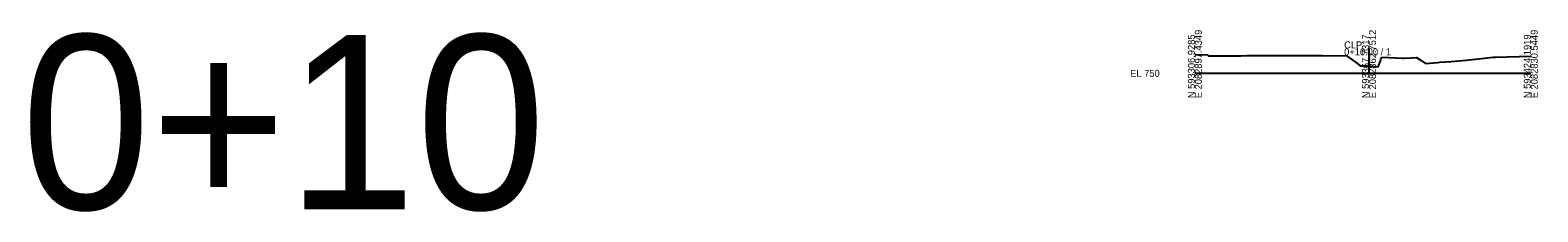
# Model space of a CAD drawing. Extents: x -577 to 1138, y -35 to 4556.
# Drawn here: x -468 to 138, y 944 to 1017 of the extents above; entities that cross this region are included whole.
import ezdxf

# ---------------------------------------------------------------- set-up
doc = ezdxf.new("R2010")
doc.units = 0
for name, color, linetype in [('GK_Cells', 7, 'Continuous'), ('SC_Scratch1', 7, 'Continuous'), ('XS_X_Ground_Line', 7, 'Continuous')]:
    doc.layers.add(name, color=color, linetype=linetype)

msp = doc.modelspace()

# ---------------------------------------------------------------- linework, layer by layer
at = {"layer": 'GK_Cells'}
for p, q in [((70, 1000), (70, 1010)), ((0, 1000), (70, 1000)), ((70, 1000), (135, 1000))]:
    msp.add_line(p, q, dxfattribs=at)
at = {"layer": 'XS_X_Ground_Line'}
for p, q in [((0, 1007.55), (0.53, 1007.54)), ((0.53, 1007.54), (5.17, 1007.37)), ((5.17, 1007.37), (5.41, 1007.02)), ((5.41, 1007.02), (6.27, 1007.01)), ((6.27, 1007.01), (6.34, 1007.01)), ((6.34, 1007.01), (6.45, 1007.01)), ((6.45, 1007.01), (6.86, 1007)), ((6.86, 1007), (8.05, 1007)), ((8.05, 1007), (17.53, 1007.06)), ((17.53, 1007.06), (18.52, 1007.07)), ((18.52, 1007.07), (20.79, 1007.09)), ((20.79, 1007.09), (25.91, 1007.12)), ((25.91, 1007.12), (27.9, 1007.13)), ((27.9, 1007.13), (28.58, 1007.14)), ((28.58, 1007.14), (30.18, 1007.15)), ((30.18, 1007.15), (31.22, 1007.16)), ((31.22, 1007.16), (35.41, 1007.13)), ((35.41, 1007.13), (37.41, 1007.14)), ((37.41, 1007.14), (39.79, 1007.15)), ((39.79, 1007.15), (40.77, 1007.16)), ((40.77, 1007.16), (42.88, 1007.14)), ((42.88, 1007.14), (46.5, 1007.12)), ((46.5, 1007.12), (48.3, 1007.11)), ((48.3, 1007.11), (49.15, 1007.11)), ((49.15, 1007.11), (51.17, 1007.09)), ((51.17, 1007.09), (52.43, 1007.08)), ((52.43, 1007.08), (60.75, 1007.16)), ((60.75, 1007.16), (64.07, 1004.91)), ((74.8, 1005.6), (75.16, 1006.48)), ((75.16, 1006.48), (83.39, 1006.07)), ((83.39, 1006.07), (83.45, 1006.08)), ((83.45, 1006.08), (84.17, 1006.11)), ((84.17, 1006.11), (86.99, 1006.23)), ((86.99, 1006.23), (88.94, 1006.31)), ((88.94, 1006.31), (89.02, 1006.32)), ((89.02, 1006.32), (90.92, 1005.13)), ((113.98, 1005.79), (119.95, 1006.5)), ((119.95, 1006.5), (120.63, 1006.51)), ((120.63, 1006.51), (120.71, 1006.52)), ((120.63, 1006.51), (120.63, 1006.51)), ((120.71, 1006.52), (120.73, 1006.52)), ((120.73, 1006.52), (120.78, 1006.52)), ((120.78, 1006.52), (120.81, 1006.52)), ((120.81, 1006.52), (120.82, 1006.52)), ((120.82, 1006.52), (120.83, 1006.52)), ((120.83, 1006.52), (120.85, 1006.52)), ((120.85, 1006.52), (135, 1006.91)), ((64.07, 1004.91), (64.18, 1004.82)), ((64.18, 1004.82), (64.47, 1004.59)), ((64.47, 1004.59), (64.63, 1004.46)), ((64.63, 1004.46), (66.4, 1003)), ((66.4, 1003), (66.86, 1003)), ((66.86, 1003), (69.2, 1002.97)), ((69.2, 1002.97), (73.61, 1002.67)), ((73.61, 1002.67), (74.54, 1004.95)), ((74.54, 1004.95), (74.8, 1005.6)), ((90.92, 1005.13), (92.72, 1003.92)), ((92.72, 1003.92), (97.56, 1004.41)), ((97.56, 1004.41), (98.42, 1004.45)), ((98.42, 1004.45), (102.99, 1004.81)), ((102.99, 1004.81), (108.97, 1005.25)), ((108.97, 1005.25), (113.98, 1005.79))]:
    msp.add_line(p, q, dxfattribs=at)

# ---------------------------------------------------------------- texts
at = {"layer": 'GK_Cells'}
for s, p in [('N 593306.9285', (0, 990)), ('E 2082897.4349', (2.8, 990)), ('N 593367.7317', (70, 990)), ('E 2082862.7512', (72.8, 990)), ('N 593424.1919', (135, 990)), ('E 2082830.5449', (137.8, 990))]:
    msp.add_text(s, height=2.8, rotation=90, dxfattribs=at).set_placement(p)
for s, p in [('CLP_', (60, 1010)), ('0+10.00 / 1', (60, 1007.2)), ('EL 750', (-26, 998.6))]:
    msp.add_text(s, height=2.8, dxfattribs=at).set_placement(p)
at = {"layer": 'SC_Scratch1'}
msp.add_text('0+10', height=70, dxfattribs=at).set_placement((-471.72, 945.43))

doc.saveas('drawing.dxf')
